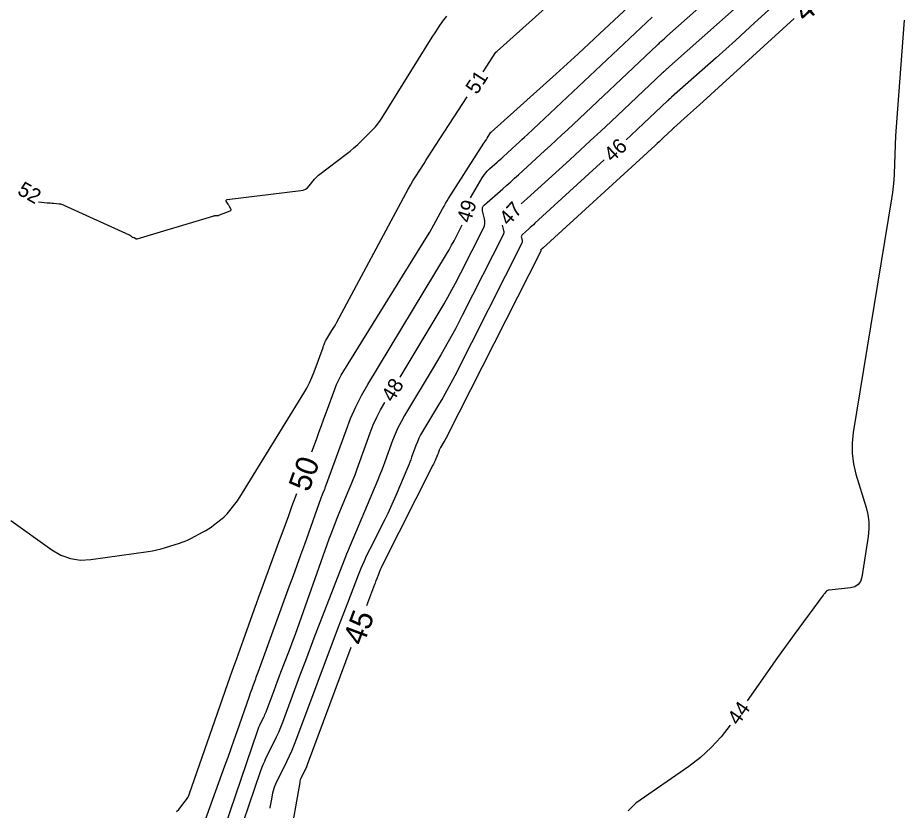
# Model space of a CAD drawing. Extents: x 2384780 to 2405861, y 547869 to 573706.
# Drawn here: x 2389896.7 to 2390016.5, y 552241 to 552348.1 of the extents above; entities that cross this region are included whole.
import ezdxf

# ---------------------------------------------------------------- set-up
doc = ezdxf.new("R2010")
doc.units = 0
doc.layers.add('Old_Level_60', color=7, linetype='Continuous')
doc.layers.add('Old_Level_61', color=7, linetype='Continuous')

msp = doc.modelspace()

# ---------------------------------------------------------------- linework, layer by layer
at = {"layer": 'Old_Level_60'}
for points in [[(2389948.40875, 552299.529), (2389953.54525, 552308.0445), (2389954.355, 552309.4155), (2389955.13875, 552310.80075), (2389955.89675, 552312.20025), (2389956.629, 552313.614), (2389959.67525, 552319.6335), (2389959.80075, 552319.943), (2389959.86725, 552320.25925), (2389959.8745, 552320.5825), (2389959.823, 552320.9125), (2389959.55825, 552322.0015), (2389959.531, 552322.2255), (2389959.56325, 552322.43075), (2389959.65475, 552322.6175), (2389959.8055, 552322.78525), (2389962.292, 552324.9695), (2389962.8235, 552325.43875), (2389963.353, 552325.91075), (2389963.88, 552326.38525), (2389964.4045, 552326.8625), (2389967.975, 552330.125), (2389968.739, 552330.8255), (2389969.50025, 552331.52875), (2389970.259, 552332.23475), (2389971.01525, 552332.94325), (2389983.14725, 552344.35275), (2389983.2755, 552344.47325), (2389983.40375, 552344.594), (2389983.532, 552344.7145), (2389983.66025, 552344.83525), (2389984.079, 552345.22925), (2389984.16925, 552345.31325), (2389984.25975, 552345.39675), (2389984.351, 552345.4795), (2389984.44275, 552345.56175), (2389994.68475, 552354.667)], [(2389998.71775, 552353.84325), (2389984.8095, 552341.4785), (2389984.7165, 552341.39525), (2389984.62375, 552341.31125), (2389984.53175, 552341.2265), (2389984.4405, 552341.141), (2389984.14275, 552340.86125), (2389984.079, 552340.80125), (2389984.01525, 552340.74125), (2389983.9515, 552340.68125), (2389983.88775, 552340.62125), (2389976.91225, 552334.06125), (2389975.5245, 552332.76075), (2389974.132, 552331.4655), (2389972.735, 552330.175), (2389971.33325, 552328.8895), (2389965.57275, 552323.62575), (2389965.176, 552323.265), (2389964.791, 552322.91825)], [(2390003.875, 552354.26525), (2389996.318, 552347.3635), (2389995.02075, 552346.18275), (2389993.71925, 552345.00625), (2389992.41425, 552343.834), (2389991.105, 552342.66625), (2389985.09725, 552337.32525), (2389985.04225, 552337.276), (2389984.98725, 552337.226), (2389984.93275, 552337.176), (2389984.87875, 552337.12525), (2389984.70225, 552336.9595), (2389984.6645, 552336.924), (2389984.62675, 552336.8885), (2389984.589, 552336.853), (2389984.55125, 552336.8175), (2389980.5095, 552333.0165), (2389979.642, 552332.2035), (2389978.95, 552331.55975)], [(2389959.651, 552340.75725), (2389961.363, 552343.40125), (2389961.375, 552343.418), (2389961.3885, 552343.43275), (2389961.40375, 552343.44625), (2389961.4205, 552343.458), (2389961.478, 552343.49375), (2389961.49, 552343.50175), (2389961.50175, 552343.51025), (2389961.513, 552343.519), (2389961.524, 552343.5285), (2389968.01525, 552349.3605)], [(2389899.53925, 552323.181), (2389900.7365, 552323.07875), (2389900.95975, 552323.0595), (2389901.183, 552323.0395), (2389901.406, 552323.01875), (2389901.629, 552322.9975), (2389902.3575, 552322.92675), (2389902.512, 552322.90525), (2389902.663, 552322.8715), (2389902.811, 552322.8255), (2389902.95525, 552322.76675), (2389911.80525, 552318.75), (2389911.85475, 552318.72525), (2389911.90175, 552318.6965), (2389911.94625, 552318.66425), (2389911.98825, 552318.62825), (2389912.1215, 552318.50425), (2389912.15125, 552318.4795), (2389912.18325, 552318.459), (2389912.21725, 552318.44225), (2389912.25375, 552318.4295), (2389912.4295, 552318.3785), (2389912.4665, 552318.36625), (2389912.50225, 552318.3515), (2389912.537, 552318.33375), (2389912.57025, 552318.31325), (2389912.727, 552318.209), (2389912.76125, 552318.19075), (2389912.79675, 552318.18125), (2389912.8335, 552318.18), (2389912.87175, 552318.1875), (2389923.0975, 552321.27125), (2389923.17875, 552321.293), (2389923.261, 552321.30975), (2389923.344, 552321.3215), (2389923.42775, 552321.32825), (2389923.70325, 552321.34175), (2389923.76175, 552321.347), (2389923.81925, 552321.35675), (2389923.876, 552321.37125), (2389923.9315, 552321.39025), (2389925.45725, 552321.98175), (2389925.544, 552322.0305), (2389925.589, 552322.09375), (2389925.592, 552322.17125), (2389925.55325, 552322.263), (2389925.358, 552322.586), (2389925.316, 552322.65525), (2389925.27375, 552322.72425), (2389925.2315, 552322.79325), (2389925.189, 552322.862), (2389924.9275, 552323.2835), (2389924.89175, 552323.364), (2389924.89625, 552323.4255), (2389924.941, 552323.46725), (2389925.0265, 552323.49), (2389934.99225, 552324.7165), (2389935.32625, 552324.78875), (2389935.628, 552324.91875), (2389935.8975, 552325.10675), (2389936.1345, 552325.35275), (2389936.85625, 552326.25125), (2389937.01625, 552326.43825), (2389937.18675, 552326.61425), (2389937.368, 552326.7795), (2389937.55975, 552326.934), (2389941.11175, 552329.61725), (2389941.652, 552330.04), (2389942.17675, 552330.4805), (2389942.68625, 552330.93875), (2389943.18025, 552331.41475), (2389944.76875, 552332.99875), (2389945.09825, 552333.34675), (2389945.406, 552333.712), (2389945.69225, 552334.0945), (2389945.9565, 552334.4945), (2389952.7545, 552345.44725), (2389953.219, 552346.172), (2389953.70325, 552346.883), (2389954.20725, 552347.58), (2389954.7315, 552348.263)], [(2389957.9465, 552323.752), (2389959.4935, 552326.4205), (2389959.70975, 552326.76125), (2389959.9515, 552327.08125), (2389960.2185, 552327.3805), (2389960.51075, 552327.65875), (2389961.507, 552328.534), (2389961.72, 552328.722), (2389961.932, 552328.911), (2389962.14325, 552329.10125), (2389962.3535, 552329.29225), (2389964.1145, 552330.9015), (2389964.49125, 552331.247), (2389964.86675, 552331.594), (2389965.241, 552331.942), (2389965.614, 552332.2915), (2389982.4615, 552348.13575)], [(2390016.5415, 552347.75075), (2390015.6085, 552335.73775), (2390015.5205, 552334.5315), (2390015.44325, 552333.3245), (2390015.37725, 552332.117), (2390015.32225, 552330.90875), (2390015.16075, 552326.961), (2390015.11325, 552326.11625), (2390015.04025, 552325.27425), (2390014.94175, 552324.43475), (2390014.8175, 552323.598), (2390009.64025, 552292.01525), (2390009.48925, 552290.6005), (2390009.50175, 552289.19675), (2390009.67775, 552287.804), (2390010.0175, 552286.42225), (2390011.394, 552281.92675), (2390011.6325, 552280.95925), (2390011.75825, 552279.984), (2390011.771, 552279.00075), (2390011.671, 552278.0095), (2390010.8065, 552272.5105), (2390010.632, 552271.923), (2390010.31725, 552271.484), (2390009.862, 552271.19325), (2390009.26625, 552271.0505), (2390006.37775, 552270.7535), (2390006.272, 552270.7335), (2390006.175, 552270.69625), (2390006.0865, 552270.6415), (2390006.00675, 552270.5695), (2390005.76, 552270.30575), (2390005.708, 552270.24825), (2390005.658, 552270.18975), (2390005.6095, 552270.1295), (2390005.56275, 552270.06775), (2390001.66875, 552264.7545), (2390000.83725, 552263.61375), (2390000.0115, 552262.469), (2389999.1915, 552261.32), (2389998.377, 552260.167), (2389995.29725, 552255.783)], [(2389895.81725, 552280.1275), (2389901.3515, 552276.172), (2389902.5695, 552275.4555), (2389903.852, 552275.0015), (2389905.199, 552274.80975), (2389906.6105, 552274.8805), (2389914.37, 552275.9655), (2389914.96275, 552276.0605), (2389915.55, 552276.17925), (2389916.132, 552276.3215), (2389916.70875, 552276.4875), (2389918.584, 552277.0685), (2389918.982, 552277.202), (2389919.3725, 552277.354), (2389919.7555, 552277.524), (2389920.13075, 552277.71225), (2389921.81875, 552278.60925), (2389922.17575, 552278.809), (2389922.5225, 552279.024), (2389922.8595, 552279.25425), (2389923.18675, 552279.4995), (2389924.34425, 552280.408), (2389924.58575, 552280.60925), (2389924.8145, 552280.82325), (2389925.0305, 552281.0505), (2389925.2335, 552281.2905), (2389926.075, 552282.34525), (2389926.25175, 552282.57375), (2389926.42125, 552282.80725), (2389926.58375, 552283.046), (2389926.739, 552283.2895), (2389935.40225, 552297.34875), (2389935.80375, 552298.03875), (2389936.16875, 552298.7465), (2389936.497, 552299.472), (2389936.78875, 552300.21525), (2389937.99725, 552303.5395), (2389938.031, 552303.632), (2389938.06475, 552303.7245), (2389938.0985, 552303.81725), (2389938.1325, 552303.90975), (2389938.2435, 552304.212), (2389938.26875, 552304.276), (2389938.29725, 552304.3385), (2389938.329, 552304.3995), (2389938.36375, 552304.45875), (2389939.19275, 552305.79475), (2389939.36825, 552306.0825), (2389939.53875, 552306.37275), (2389939.705, 552306.66575), (2389939.86625, 552306.9615), (2389949.1695, 552324.327), (2389949.4835, 552324.8995), (2389949.80825, 552325.46575), (2389950.144, 552326.0255), (2389950.4905, 552326.57875), (2389951.64075, 552328.376), (2389951.88725, 552328.76075), (2389952.1345, 552329.1455), (2389952.38225, 552329.52975), (2389952.6305, 552329.91375), (2389957.477, 552337.3995)], [(2389976.0045, 552328.8535), (2389966.6345, 552320.29175), (2389966.41925, 552320.09575), (2389966.203, 552319.901), (2389965.98575, 552319.70725), (2389965.7675, 552319.51475), (2389964.939, 552318.787), (2389964.85875, 552318.6975), (2389964.81, 552318.59825), (2389964.79275, 552318.489), (2389964.80725, 552318.36975), (2389964.906, 552317.964), (2389964.9195, 552317.878), (2389964.9175, 552317.7935), (2389964.90025, 552317.711), (2389964.8675, 552317.63025), (2389955.79425, 552299.703), (2389955.27725, 552298.7045), (2389954.742, 552297.71625), (2389954.1885, 552296.738), (2389953.61675, 552295.77), (2389951.44525, 552292.16975), (2389951.187, 552291.7175), (2389950.952, 552291.25425), (2389950.74, 552290.78), (2389950.55075, 552290.29475), (2389949.97025, 552288.692), (2389949.8435, 552288.3495), (2389949.71275, 552288.00875), (2389949.57725, 552287.6695), (2389949.4375, 552287.332), (2389947.82925, 552283.5195), (2389947.47775, 552282.70575), (2389947.11225, 552281.89825), (2389946.73325, 552281.0975), (2389946.34025, 552280.30275), (2389944.3125, 552276.29075), (2389943.889, 552275.42625), (2389943.4875, 552274.552), (2389943.108, 552273.66775), (2389942.75025, 552272.774), (2389941.29225, 552268.99525), (2389940.981, 552268.185), (2389940.67175, 552267.374), (2389940.36475, 552266.56225), (2389940.05975, 552265.74975), (2389934.428, 552250.68675), (2389934.117, 552249.88675), (2389933.786, 552249.09525), (2389933.4345, 552248.31275), (2389933.06275, 552247.539), (2389931.56675, 552244.52375), (2389931.435, 552244.2325), (2389931.325, 552243.934), (2389931.237, 552243.6285), (2389931.17075, 552243.31575), (2389930.99, 552242.28225), (2389930.9505, 552242.061), (2389930.90975, 552241.84), (2389930.86775, 552241.61925), (2389930.8245, 552241.3985), (2389930.8, 552241.2755)], [(2389919.2745, 552231.86775), (2389924.742, 552247.0275), (2389925.1575, 552248.18425), (2389925.57025, 552249.342), (2389925.98025, 552250.501), (2389926.387, 552251.661), (2389928.05325, 552256.42875), (2389928.16675, 552256.75225), (2389928.2815, 552257.0755), (2389928.397, 552257.3985), (2389928.51325, 552257.721), (2389928.89525, 552258.77425), (2389928.97725, 552258.99975), (2389929.05925, 552259.2255), (2389929.1415, 552259.451), (2389929.224, 552259.6765), (2389933.4845, 552271.31075), (2389933.99675, 552272.715), (2389934.506, 552274.12025), (2389935.012, 552275.52675), (2389935.51475, 552276.9345), (2389937.74675, 552283.205), (2389937.8015, 552283.355), (2389937.85825, 552283.50425), (2389937.91725, 552283.65275), (2389937.97825, 552283.8005), (2389938.18125, 552284.2815), (2389938.224, 552284.38475), (2389938.2655, 552284.48875), (2389938.3055, 552284.593), (2389938.34425, 552284.698), (2389941.09975, 552292.3055), (2389941.72825, 552293.9175), (2389942.433, 552295.493), (2389943.21425, 552297.03225), (2389944.0715, 552298.53525), (2389954.6735, 552316.11125), (2389955.02925, 552316.71375), (2389955.37375, 552317.3225), (2389955.707, 552317.93775), (2389956.02875, 552318.559), (2389956.803, 552320.08875)], [(2389962.21375, 552320.05775), (2389962.38875, 552319.33825), (2389962.41375, 552319.17975), (2389962.41, 552319.0245), (2389962.37825, 552318.8725), (2389962.318, 552318.72375), (2389956.8085, 552307.83775), (2389955.88, 552306.045), (2389954.919, 552304.27025), (2389953.92525, 552302.514), (2389952.8985, 552300.7755), (2389948.99875, 552294.31075), (2389948.5355, 552293.4985), (2389948.11325, 552292.66675), (2389947.7325, 552291.81525), (2389947.39275, 552290.944), (2389946.35025, 552288.066), (2389946.123, 552287.451), (2389945.88775, 552286.83875), (2389945.64475, 552286.22975), (2389945.39375, 552285.624), (2389941.295, 552275.90725), (2389941.2815, 552275.87575), (2389941.26725, 552275.8445), (2389941.2525, 552275.8135), (2389941.23725, 552275.78275), (2389941.18675, 552275.6825), (2389941.17625, 552275.661), (2389941.166, 552275.639), (2389941.15675, 552275.617), (2389941.14775, 552275.59475), (2389937.565, 552266.308), (2389936.9105, 552264.60475), (2389936.26025, 552262.89975), (2389935.61475, 552261.19325), (2389934.9735, 552259.48475), (2389932.50175, 552252.874), (2389932.238, 552252.19525), (2389931.957, 552251.52375), (2389931.659, 552250.85975), (2389931.3435, 552250.20325), (2389930.2855, 552248.07075), (2389930.0665, 552247.61075), (2389929.863, 552247.144), (2389929.67525, 552246.67075), (2389929.503, 552246.19125), (2389927.209, 552239.45975)], [(2389921.05775, 552228.022), (2389929.12, 552251.68125), (2389929.217, 552251.95125), (2389929.32275, 552252.2175), (2389929.4375, 552252.48025), (2389929.56075, 552252.7395), (2389929.97775, 552253.57975), (2389930.06475, 552253.761), (2389930.147, 552253.944), (2389930.2245, 552254.12925), (2389930.29725, 552254.31675), (2389931.374, 552257.1965), (2389931.6055, 552257.81325), (2389931.8385, 552258.4295), (2389932.07325, 552259.045), (2389932.3095, 552259.66), (2389933.3745, 552262.42025), (2389933.60075, 552263.01225), (2389933.823, 552263.606), (2389934.0415, 552264.201), (2389934.256, 552264.7975), (2389938.83125, 552277.651), (2389939.1725, 552278.58825), (2389939.527, 552279.52075), (2389939.895, 552280.44775), (2389940.276, 552281.36975), (2389941.543, 552284.373), (2389941.81025, 552285.01825), (2389942.069, 552285.66675), (2389942.3195, 552286.3185), (2389942.5615, 552286.9735), (2389944.3775, 552291.98725), (2389944.79175, 552293.0495), (2389945.25625, 552294.088), (2389945.771, 552295.1025), (2389946.336, 552296.09275), (2389946.34275, 552296.10375)], [(2389992.99775, 552252.51), (2389991.78625, 552250.934), (2389990.4505, 552249.47775), (2389988.99225, 552248.144), (2389987.4115, 552246.933), (2389980.285, 552241.94275), (2389979.2155, 552240.93775)]]:
    msp.add_lwpolyline(points, dxfattribs=at)
at = {"layer": 'Old_Level_61'}
for points in [[(2389936.48775, 552289.42925), (2389937.09625, 552291.103), (2389937.43575, 552292.03575), (2389937.77625, 552292.96825), (2389938.11725, 552293.9005), (2389938.459, 552294.8325), (2389939.57675, 552297.8765), (2389939.83225, 552298.521), (2389940.11925, 552299.15), (2389940.438, 552299.76375), (2389940.7885, 552300.362), (2389952.1055, 552318.60075), (2389952.40625, 552319.09375), (2389952.69875, 552319.5915), (2389952.9835, 552320.09375), (2389953.26025, 552320.6005), (2389954.15125, 552322.26375), (2389954.3455, 552322.618), (2389954.5465, 552322.9685), (2389954.75425, 552323.315), (2389954.96875, 552323.6575), (2389959.7395, 552331.1125), (2389959.849, 552331.28325), (2389959.9585, 552331.454), (2389960.0685, 552331.62425), (2389960.1785, 552331.7945), (2389960.691, 552332.586), (2389960.692, 552332.5875), (2389960.693, 552332.5885), (2389960.69425, 552332.58975), (2389960.6955, 552332.5905), (2389960.7, 552332.5935), (2389960.701, 552332.594), (2389960.702, 552332.59475), (2389960.703, 552332.5955), (2389960.70375, 552332.59625), (2389969.50725, 552340.50575), (2389970.9895, 552341.845), (2389972.464, 552343.19275), (2389973.93075, 552344.54875), (2389975.38975, 552345.913), (2389981.7755, 552351.9185)], [(2390001.672, 552347.98125), (2389988.8855, 552336.3035), (2389988.481, 552335.93525), (2389988.075, 552335.56825), (2389987.66775, 552335.2025), (2389987.25925, 552334.83825), (2389985.38525, 552333.172), (2389985.368, 552333.1565), (2389985.35075, 552333.141), (2389985.33375, 552333.1255), (2389985.317, 552333.1095), (2389985.262, 552333.058), (2389985.25, 552333.04675), (2389985.23825, 552333.03575), (2389985.2265, 552333.02475), (2389985.21475, 552333.0135), (2389983.954, 552331.82775), (2389983.68325, 552331.57425), (2389983.41175, 552331.3215), (2389983.13925, 552331.07), (2389982.866, 552330.81925), (2389967.6965, 552316.95775), (2389967.66225, 552316.92675), (2389967.62825, 552316.896), (2389967.59375, 552316.86525), (2389967.55925, 552316.835), (2389967.42825, 552316.71975), (2389967.41575, 552316.70575), (2389967.408, 552316.69), (2389967.40525, 552316.67275), (2389967.4075, 552316.654), (2389967.42325, 552316.58975), (2389967.42525, 552316.57625), (2389967.425, 552316.56275), (2389967.42225, 552316.54975), (2389967.417, 552316.537), (2389954.78025, 552291.56825), (2389954.6745, 552291.364), (2389954.56525, 552291.16225), (2389954.452, 552290.96225), (2389954.33525, 552290.7645), (2389953.8915, 552290.02875), (2389953.83875, 552289.93625), (2389953.79075, 552289.84175), (2389953.74725, 552289.74475), (2389953.70875, 552289.6455), (2389953.59, 552289.318), (2389953.56425, 552289.248), (2389953.5375, 552289.1785), (2389953.50975, 552289.10925), (2389953.48125, 552289.04025), (2389953.1525, 552288.261), (2389953.08075, 552288.09475), (2389953.006, 552287.92975), (2389952.9285, 552287.76625), (2389952.84825, 552287.60375), (2389945.96225, 552273.9785), (2389945.84525, 552273.7395), (2389945.7345, 552273.498), (2389945.6295, 552273.25375), (2389945.53075, 552273.00675), (2389945.21775, 552272.19575), (2389945.151, 552272.02175), (2389945.0845, 552271.84775), (2389945.01875, 552271.6735), (2389944.95325, 552271.499), (2389943.871, 552268.60475)], [(2389927.2275, 552264.014), (2389928.70225, 552268.0805), (2389929.0185, 552268.952), (2389929.3355, 552269.823), (2389929.65325, 552270.69375), (2389929.9715, 552271.56425), (2389932.03525, 552277.2), (2389932.47725, 552278.40775), (2389932.91825, 552279.61575), (2389933.35875, 552280.824), (2389933.7985, 552282.0325), (2389934.43775, 552283.79025)], [(2389918.20375, 552240.83), (2389918.4935, 552241.124), (2389919.37375, 552242.23625), (2389919.55125, 552242.4805), (2389919.70675, 552242.73725), (2389919.84, 552243.00575), (2389919.95125, 552243.28675), (2389925.451, 552259.02425), (2389925.88975, 552260.27375), (2389926.332, 552261.52175), (2389926.778, 552262.7685), (2389927.2275, 552264.014)], [(2389941.76975, 552262.98475), (2389935.8405, 552247.1255), (2389935.748, 552246.8875), (2389935.64925, 552246.652), (2389935.54475, 552246.419), (2389935.43425, 552246.18875), (2389935.063, 552245.4405), (2389934.9895, 552245.27825), (2389934.92825, 552245.112), (2389934.87925, 552244.94175), (2389934.84225, 552244.7675), (2389933.47, 552236.9215)]]:
    msp.add_lwpolyline(points, dxfattribs=at)

# ---------------------------------------------------------------- texts
at = {"layer": 'Old_Level_60'}
for s, rotation, p in [('51', 57.0792667, (2389958.78725, 552337.583)), ('46', 42.5736306, (2389977.0665, 552328.46575)), ('52', 330.1737333, (2389896.557, 552324.30775)), ('49', 72.6638194, (2389957.90475, 552320.225)), ('47', 47.9824917, (2389963.07575, 552319.86025)), ('48', 58.9017278, (2389947.45525, 552296.01225)), ('44', 54.9088694, (2389994.11475, 552252.3605))]:
    msp.add_text(s, height=2, rotation=rotation, dxfattribs=at).set_placement(p)
at = {"layer": 'Old_Level_61'}
for s, rotation, p in [('45', 42.4050611, (2390003.19825, 552347.34375)), ('50', 70.0203528, (2389936.0655, 552283.8775)), ('45', 69.5003028, (2389943.419, 552263.11225))]:
    msp.add_text(s, height=3, rotation=rotation, dxfattribs=at).set_placement(p)

doc.saveas('drawing.dxf')
